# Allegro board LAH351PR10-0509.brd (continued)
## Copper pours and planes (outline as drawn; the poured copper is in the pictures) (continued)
LX2_NVVDD on BOTTOM (solid shape): 34.61,50.45 34.61,48.86 34.54,48.8 32.96,48.8 32.83,48.92 32.83,50.38 32.96,50.51 34.54,50.51
LX3_NVVDD on TOP (solid shape): 42.48,50.23 43.27,50.23 43.27,51.11 44.62,51.11 44.83,50.89 44.83,47.21 44.54,46.92 39.2,46.92 38.93,46.64 38.93,45.49 38.86,45.43 38.23,45.43 38.16,45.49 38.16,50.64 38.63,51.11 42.48,51.11
LX3_NVVDD on BOTTOM (solid shape): 42.29,50.45 42.29,48.86 42.23,48.8 40.64,48.8 40.51,48.92 40.51,50.38 40.64,50.51 42.23,50.51
LX4_NVVDD on TOP (solid shape): 50.24,50.24 50.95,50.24 50.95,51.11 52.24,51.11 52.45,50.89 52.45,47.21 52.16,46.92 46.82,46.92 46.55,46.64 46.55,45.49 46.48,45.43 45.85,45.43 45.78,45.49 45.78,50.64 46.25,51.11 50.24,51.11
LX4_NVVDD on BOTTOM (solid shape): 49.97,50.45 49.97,48.86 49.91,48.8 48.32,48.8 48.2,48.92 48.2,50.38 48.32,50.51 49.91,50.51
LX5_NVVDD on TOP (solid shape): 60.13,51.13 60.13,47.21 59.84,46.92 54.51,46.92 54.23,46.64 54.23,45.49 54.17,45.43 53.53,45.43 53.47,45.49 53.47,50.64 54.13,51.3 57.9,51.3 57.96,51.24 57.96,50.27 58.67,50.27 58.67,51.26 58.74,51.32 59.94,51.32
LX5_NVVDD on BOTTOM (solid shape): 57.78,50.57 57.78,48.99 57.72,48.92 56.13,48.92 56.01,49.05 56.01,50.51 56.13,50.64 57.72,50.64
LX6_NVVDD on TOP (solid shape): 65.76,51.2 65.76,50.33 66.47,50.33 66.47,51.18 66.54,51.25 67.78,51.25 67.88,51.15 67.88,47.27 67.5,46.89 62.19,46.89 61.98,46.68 61.98,45.43 61.91,45.37 61.15,45.37 61.09,45.43 61.09,50.83 61.53,51.27 65.68,51.27
LX6_NVVDD on BOTTOM (solid shape): 65.6,50.51 65.6,48.92 65.53,48.86 63.94,48.86 63.82,48.99 63.82,50.45 63.94,50.57 65.53,50.57
LX7_NVVDD on TOP (solid shape): 73.52,50.39 74.28,50.39 74.28,51.37 75.58,51.37 75.63,51.32 75.63,47.08 75.5,46.95 73.53,46.95 73.41,46.83 69.72,46.83 69.53,46.64 69.53,45.49 69.47,45.43 68.71,45.43 68.52,45.62 68.52,50.7 69.19,51.37 73.52,51.37
LX7_NVVDD on BOTTOM (solid shape): 73.34,50.7 73.34,49.11 73.28,49.05 71.69,49.05 71.56,49.18 71.56,50.64 71.69,50.76 73.28,50.76
LX8_NVVDD on TOP: 79.25,89.82 80.26,89.82 80.58,89.5 80.58,80.61 78.23,78.26 78.23,75.21 77.98,74.96 76.83,74.96 76.71,75.08 76.71,78.77 76.58,78.89 75.37,78.89 75.31,78.96 75.31,81.08 77.76,83.53 78.17,83.53 78.23,83.59 78.99,83.59 79.06,83.66 79.06,84.42 78.99,84.48 78.23,84.48 78.17,84.55 78.17,87.47 79.12,88.42 79.12,89.69
LX_1.0VS_VGAP on TOP (solid shape): 71.34,110.02 71.34,109.35 71.41,109.28 71.63,109.28 71.74,109.17 71.74,108.73 71.69,108.68 70.68,108.68 70.39,108.97 69.69,108.97 69.61,109.04 69.61,110.06 69.71,110.16 71.19,110.16
LX_1.0VS_VGAP on BOTTOM (solid shape): 72.29,109.34 72.29,105.91 72.04,105.66 71.53,105.66 71.47,105.72 71.47,107.47 70.93,108.01 68.23,108.01 67.94,108.3 67.94,109.76 68.01,109.82 71.82,109.82
LX_1.0VS_VGAP on IN4 (solid shape): 71.7,109.07 71.7,108.09 71.59,107.98 71.25,107.98 71.18,108.04 71.18,108.64 71.07,108.75 70.64,108.75 70.51,108.88 70.51,109.16 70.65,109.3 71.48,109.3
LX_3V on TOP: 65.02,23.4 66,22.42 68.45,22.42 68.47,22.41 68.47,21.88 68.43,21.85 67.09,21.85 66.9,21.65 66.9,19.62 66.7,19.42 63.31,19.42 63.22,19.51 63.22,21.82 64.26,22.86 64.26,24.44 64.34,24.51 64.92,24.51 65.02,24.41
LX_3V on BOTTOM: 65.07,23.9 65.56,23.9 65.61,23.85 65.61,22.84 64.9,22.13 64.14,22.13 63.25,23.01 63.25,23.03 63.14,23.03 62.92,23.26 62.92,24.27 63.02,24.37 64.6,24.37
LX_5V on TOP (solid shape): 56.2,25.43 56.2,20.16 55.18,19.14 55.18,16.98 54.23,16.03 52.26,16.03 52.07,16.22 52.07,19.84 52.48,20.25 54.32,20.25 55.63,21.55 55.63,25.43 55.75,25.55 56.07,25.55
LX_5V on BOTTOM (solid shape): 57.09,17.93 58.36,17.93 58.48,17.81 58.48,17.17 58.36,17.05 53.98,17.05 53.85,17.17 53.85,18.57 54.28,19 56.02,19
LX_+1.8VGS on TOP: 48.83,7.08 48.83,6.57 48.96,6.44 51.18,6.44 51.31,6.31 51.31,5.11 51.44,4.98 52.9,4.98 53.02,5.11 53.02,8.66 52.64,9.04 52.64,9.81 52.58,9.87 50.42,9.87 50.36,9.81 50.36,8.6
LX_CHG on BOTTOM (solid shape): 42.28,18.56 42.38,18.56 42.53,18.4 43.61,18.4 43.69,18.33 43.69,18.19 43.64,18.14 42.43,18.14 42.39,18.1 42.21,18.1 41.97,18.34 41.67,18.34 41.57,18.44 41.57,18.7 41.69,18.82 42.01,18.82
LX_CHG on TOP: 35.12,25.44 35.12,23.13 36.2,22.04 39.71,22.04 42.86,18.89 42.86,18.44 42.48,18.06 42.04,18.06 39.71,20.39 31.26,20.39 30.66,21 30.66,22.19 30.48,22.37 30.48,25.49 30.62,25.63 34.92,25.63
LX_CHG on BOTTOM: 38.61,21.36 39.5,21.36 39.62,21.24 39.62,20.79 39.5,20.67 37.02,20.67 36.35,21.34 35.42,21.34 35.18,21.1 35.18,19.84 34.99,19.65 31.75,19.65 31.37,20.03 31.37,22.28 32.25,23.16 32.25,25.33 32.71,25.78 34.44,25.78 34.95,25.27 34.95,23.89 35.32,23.52 37.85,23.52 38.23,23.14 38.23,21.74
LX_VCCIO on TOP (solid shape): 132.33,54.33 132.33,53.95 132.16,53.77 132.16,52.59 132.59,52.16 134.18,52.16 134.3,52.03 134.3,51.46 134.18,51.34 132.65,51.34 132.21,50.89 132.21,50.26 131.95,50 129.67,50 129.48,50.19 129.48,53.43 129.51,53.46 129.51,54.42 129.73,54.64 132.03,54.64
LX_VCCIO on BOTTOM (solid shape): 132.33,54.57 132.33,54.04 131.79,53.49 129.6,53.49 129.16,53.05 129.16,50.51 129.29,50.38 130,50.38 130.06,50.32 130.06,49.71 129.97,49.62 128.78,49.62 128.52,49.88 128.52,54.57 128.71,54.76 132.14,54.76
LX_VCCIO on TOP: 136.06,51.68 136.79,51.68 136.91,51.56 136.91,50.74 136.97,50.68 136.97,50.31 136.83,50.17 136.46,50.17 136.18,50.45 136.18,51.32 136,51.5 136,51.63
NVVDD_B on BOTTOM (solid shape): 21.26,37.75 21.58,37.56 21.89,37.75 25.72,37.75 26.16,37.3 26.16,35.62 26.11,35.56 15.75,35.56 15.69,35.63 15.69,37.66 15.77,37.75
NVVDD_B+ on TOP (solid shape): 52.74,44.13 52.74,41.7 52.1,41.06 52.1,38.74 51.84,38.48 49.96,38.48 49.81,38.64 49.81,41.23 50.16,41.58 50.16,42.89 50.04,43.02 48.7,43.02 48.64,43.08 48.64,44.16 48.7,44.22 52.64,44.22
NVVDD_B+ on TOP (solid shape): 37.47,44.03 37.47,42.41 36.75,42.41 36.75,41.06 36.2,40.5 36.2,38.7 36.04,38.55 34.46,38.55 34.32,38.69 34.32,41.24 34.99,41.91 34.99,42.89 34.86,43.02 33.53,43.02 33.46,43.08 33.46,44.16 33.53,44.22 37.27,44.22
NVVDD_B+ on TOP (solid shape): 79.76,43.84 79.76,41.61 79.72,41.57 79.72,39.43 79.44,39.16 76.95,39.16 76.72,39.39 71.82,39.39 71.67,39.54 71.67,40.15 71.77,40.25 72.56,40.25 73.15,40.85 73.15,42.89 73.03,43.02 71.69,43.02 71.63,43.08 71.63,44.16 71.69,44.22 76.01,44.22 76.33,44.54 79.06,44.54
NVVDD_B+ on TOP (solid shape): 45.09,44.1 45.09,41.06 44.8,40.78 44.3,40.78 44.12,40.59 44.12,38.64 43.93,38.45 41.91,38.45 41.85,38.51 41.85,39.4 42,39.55 42,41.13 42.19,41.32 42.33,41.32 42.55,41.53 42.55,42.89 42.42,43.02 41.08,43.02 41.02,43.08 41.02,44.16 41.08,44.22 44.96,44.22
NVVDD_B+ on TOP (solid shape): 29.01,43.88 29.72,43.88 30.05,43.55 30.05,41.47 29.64,41.06 29.07,41.06 28.78,40.77 28.78,38.65 28.99,38.43 29.5,38.43 29.75,38.18 29.75,34.54 29.65,34.44 26.87,34.44 26.48,34.84 26.48,35.65 25.92,36.21 25.92,39.08 26.53,39.69 26.53,40.4 26.64,40.52 26.64,41.21 27.43,42 27.43,42.89 27.3,43.02 25.97,43.02 25.91,43.08 25.91,44.16 25.97,44.22 28.66,44.22
NVVDD_B+ on BOTTOM (solid shape): 74.3,76.23 74.3,73.69 74.87,73.12 74.87,72.86 74.68,72.67 74.63,72.67 74.05,72.1 74.03,72.1 73.96,72.04 73.96,69.7 73.56,69.29 71.7,69.29 71.32,69.67 71.32,70.56 68.28,73.61 67.56,73.61 67.4,73.78 67.4,74.46 67.27,74.59 67.04,74.59 67.04,74.6 65.88,74.6 64.92,75.55 64.92,76.53 65.14,76.75 67.97,76.75 67.98,76.74 72.96,76.74 73.03,76.8 73.72,76.8
NVVDD_B+ on GND1 (solid shape): 73.91,76.61 73.91,74.13 74.61,73.43 74.8,73.43 74.93,73.31 74.93,72.93 74.74,72.74 72.83,72.74 72.52,73.05 72.52,74.13 72.9,74.51 72.9,76.67 73.09,76.86 73.66,76.86
NVVDD_B+ on TOP: 60.33,44.22 60.45,44.1 60.45,42.47 60.55,42.37 60.55,41.67 60.79,41.43 60.79,41.4 60.78,41.39 60.78,40.33 60.93,40.17 65.57,40.17 65.85,40.45 65.85,41.84 65.66,42.03 65.66,42.06 65.6,42.13 65.6,42.95 65.53,43.02 64.14,43.02 64.07,43.08 64.07,44.1 64.14,44.16 66.17,44.16 66.23,44.22 67.94,44.22 68.07,44.1 68.07,42.83 68.01,42.76 67.12,42.76 67.12,36.73 67.09,36.7 67.09,36.13 66.55,35.59 64.2,35.59 63.5,36.29 61.59,36.29 61.34,36.54 61.34,37.62 61.04,37.92 57.81,37.92 57.47,38.27 57.47,41.52 57.85,41.9 57.85,42.89 57.72,43.02 56.39,43.02 56.32,43.08 56.32,44.16 56.39,44.22
NVVDD_B+ on TOP: 73.03,76.8 73.91,76.8 74.1,76.61 74.1,73.94 74.99,73.05 74.99,71.34 74.8,71.15 71.44,71.15 71.37,71.21 71.37,74.96 71.63,75.21 72.64,75.21 72.9,75.47 72.9,76.67
NVVDD_B+ on BOTTOM: outline of 114 points within 18.67,31.65 80.07,44.35
NVVDD_B+ on IN1: 74.13,44.15 26.05,44.15 25.68,43.78 25.68,41.02 25.92,40.78 74.23,40.78 74.56,41.11 74.56,43.72
NVVDD_B+ on GND2: 72.64,72.54 74.68,72.54 74.93,72.8 74.93,73.18 74.8,73.31 74.3,73.31 74.17,73.43 74.17,74.32 73.79,74.7 72.77,74.7 72.52,74.45 72.52,72.67
NVVDD_B+ on IN2: 77.03,39.52 76.64,39.14 74.36,39.14 73.56,39.94 73.56,42.55 72.96,43.14 31.05,43.14 29.84,41.94 29.84,39.91 29.34,39.4 29.34,37.49 29.15,37.3 29.13,37.3 28.22,36.39 26.63,36.39 25.4,37.62 25.4,46.38 26.04,47.02 71.12,47.02 72.39,48.29 72.39,76.61 73.03,77.24 75.06,77.24 75.76,76.55 75.76,47.72 77.03,46.45
NVVDD_B+ on VCC: 25.59,43.61 26.27,44.29 76.98,44.29 77.41,43.86 77.41,39.57 76.67,38.83 30.57,38.83 28.09,36.35 27.03,36.35 25.59,37.79
NVVDD_B+ on IN4: 23.04,38.64 29.25,38.64 29.69,38.19 29.69,35.59 28.22,34.11 26.45,34.11 26.01,33.67 26.01,31.99 25.84,31.83 20.21,31.83 19.66,32.37 19.66,34.5 20.61,35.45 20.61,36.21
PEX_VDD_ENP on BOTTOM (solid shape): 70.55,104.23 70.55,104.1 70.36,103.91 70.36,102.96 71.17,102.15 71.17,101.6 71.02,101.45 68.15,101.45 68,101.6 68,102.19 69.34,103.53 69.34,104.1 69.53,104.29 70.48,104.29
PWM2_FBVDDQ on TOP: 15.58,40.38 16.03,40.82 16.12,40.82 16.24,40.69 16.24,40.02 15.89,39.66 13.82,39.66 13.73,39.75 13.73,40.33 13.78,40.38
SA_SW on TOP: 147.64,109.44 149.67,109.44 149.86,109.25 149.86,106.71 147.26,104.1 143.45,104.1 143.19,103.85 143.19,102.64 143.13,102.58 142.43,102.58 142.37,102.64 142.37,104.04 144.15,105.82 145.8,105.82 147.57,107.6 147.57,109.37
SNB1_NVVDD on BOTTOM (solid shape): 29.62,50.32 29.62,47.84 29.5,47.72 28.73,47.72 28.61,47.84 28.61,48.54 28.35,48.8 27.84,48.8 27.53,49.11 27.53,50.32 27.59,50.38 29.56,50.38
SNB2_NVVDD on BOTTOM (solid shape): 37.18,50.32 37.18,47.84 37.05,47.72 36.29,47.72 36.16,47.84 36.16,48.54 35.91,48.8 35.4,48.8 35.08,49.11 35.08,50.32 35.15,50.38 37.12,50.38
SNB3_NVVDD on BOTTOM (solid shape): 44.86,50.32 44.86,47.84 44.74,47.72 43.97,47.72 43.85,47.84 43.85,48.54 43.59,48.8 43.08,48.8 42.77,49.11 42.77,50.32 42.83,50.38 44.8,50.38
SNB4_NVVDD on BOTTOM (solid shape): 52.58,50.38 52.58,47.91 52.45,47.78 51.69,47.78 51.56,47.91 51.56,48.61 51.31,48.86 50.8,48.86 50.48,49.18 50.48,50.38 50.55,50.45 52.51,50.45
SNB5_NVVDD on BOTTOM (solid shape): 60.29,50.38 60.29,47.91 60.17,47.78 59.4,47.78 59.28,47.91 59.28,48.61 59.02,48.86 58.52,48.86 58.2,49.18 58.2,50.38 58.26,50.45 60.23,50.45
SNB6_NVVDD on BOTTOM (solid shape): 68.17,50.32 68.17,47.84 68.04,47.72 67.28,47.72 67.15,47.84 67.15,48.54 66.9,48.8 66.39,48.8 66.07,49.11 66.07,50.32 66.14,50.38 68.1,50.38
SNB7_NVVDD on BOTTOM (solid shape): 75.55,49.83 75.55,47.97 75.42,47.84 74.67,47.84 74.51,48 74.51,48.62 73.76,49.37 73.76,50.57 73.82,50.64 74.74,50.64
SNB8_NVVDD on TOP: 75.37,89.69 78.61,89.69 78.74,89.56 78.74,88.42 78.23,87.91 75.44,87.91 75.18,88.17 75.18,89.5
SNB_1.0VS_VGAP on TOP (solid shape): 68.94,109.97 68.94,109.07 69.25,108.77 69.25,107.9 69.2,107.85 68.14,107.85 67.96,108.03 67.96,109.92 68.06,110.01 68.9,110.01
SNB_1.2V on BOTTOM (solid shape): 150.37,61.43 150.37,60.73 150.5,60.61 151.32,60.61 151.38,60.54 151.38,59.97 151.26,59.84 148.21,59.84 148.13,59.92 148.13,61.47 148.22,61.56 150.24,61.56
SNB_+1.8VGS on TOP: 53.25,10.31 51.75,10.31 51.56,10.51 51.56,11.58 51.68,11.71 53.79,11.71 53.99,11.51 53.99,10.23 53.9,10.14 53.4,10.14 53.35,10.19 53.35,10.21
SNB_+1VALWP on BOTTOM (solid shape): 131.44,27.08 131.44,25.24 131.38,25.17 130.81,25.17 130.68,25.3 130.68,26 130.62,26.06 129.92,26.06 129.79,26.19 129.79,27.02 129.98,27.21 131.32,27.21
SNB_VCCIO on BOTTOM (solid shape): 132.14,51.97 132.14,50.95 132.08,50.89 129.54,50.89 129.41,51.02 129.41,52.73 129.79,53.11 131,53.11
SW_1.2V on TOP (solid shape): 149.43,50.52 149.43,50.13 148.95,49.65 148.95,49.42 147.87,48.34 147.8,48.34 147.68,48.47 147.68,49.16 147.87,49.35 148.11,49.35 148.37,49.62 148.37,50.47 148.54,50.64 149.31,50.64
SW_1.2V on TOP (solid shape): 150.05,61.31 150.05,56.99 150.5,56.54 151.18,56.54 151.28,56.44 151.28,55.87 151.19,55.78 150.37,55.78 150.05,55.46 150.05,53.3 149.8,53.05 145,53.05 144.82,53.23 144.82,58.14 145.22,58.55 145.22,61.37 145.48,61.62 149.73,61.62
SW_1.2V on BOTTOM (solid shape): 147.7,61.5 147.7,59.53 147.96,59.27 149.54,59.27 149.73,59.08 149.73,58.45 149.54,58.26 145.99,58.26 145.61,58.64 145.61,61.31 145.86,61.56 147.64,61.56
SW_1.2V on IN1 (solid shape): 150.18,61.11 150.18,52.92 149.54,52.29 149.54,50.19 149.35,50 148.59,50 148.4,50.19 148.4,52.42 149.1,53.11 149.1,59.65 148.72,60.04 146.05,60.04 145.8,60.29 145.8,61.11 145.99,61.31 149.99,61.31
SW_+1VALWP on TOP (solid shape): 131.38,33.77 131.38,33.43 131.76,33.05 134.75,33.05 134.81,32.98 134.81,32.54 134.62,32.35 133.41,32.35 132.65,31.59 132.65,27.33 132.4,27.08 129.29,27.08 128.97,27.4 128.97,33.68 129.22,33.94 131.22,33.94
SW_+1VALWP on BOTTOM (solid shape): 131.59,36.23 131.59,33.89 131.38,33.68 131.38,32.22 131.32,32.16 129.92,32.16 129.54,31.78 129.54,30.63 129.53,30.63 129.53,29.06 129.8,28.79 131.32,28.79 131.44,28.67 131.44,27.65 131.32,27.52 129.22,27.52 128.83,27.91 128.83,28.27 128.73,28.37 128.73,28.37 128.64,28.47 128.64,31.79 128.52,31.9 128.52,36.22 128.71,36.41 131.41,36.41
SW_+1VALWP on IN1: 134.49,30.25 135.25,30.25 135.38,30.13 135.38,29.87 135.25,29.75 133.99,29.75 133.73,30 133.73,33.81 133.54,34 131.83,34 131.19,33.37 130.87,33.37 130.81,33.43 130.81,34.13 131.38,34.7 133.92,34.7 134.37,34.25 134.37,30.38
TBT_SVR_IND on BOTTOM: 84.01,146.78 85.72,146.78 85.85,146.65 85.85,146.2 85.72,146.08 84.45,146.08 84.39,146.14 84.39,146.27 84.26,146.4 84.01,146.4 83.95,146.46 83.95,146.71
TBT_SVR_IND on IN1: 70.74,150.52 84.58,150.52 85.93,149.18 85.93,146.33 85.78,146.18 84.94,146.18 83.13,147.98 73.72,147.98 73.47,148.24 70.68,148.24 70.29,148.62 70.29,150.08
UD1_ISL95338_1 on TOP: 54.29,37.62 55.18,37.62 55.31,37.49 55.31,36.03 55.63,35.71 56.71,35.71 56.96,35.46 56.96,35.33 57.4,34.89 57.4,32.92 57.09,32.6 55.31,32.6 55.18,32.73 55.18,34.13 55.37,34.32 56.13,34.32 56.26,34.44 56.26,34.95 56.07,35.14 55.18,35.14 54.23,36.1 54.23,37.56
UD1_ISL95338_1 on TOP: 50.04,38.16 54.88,38.16 55.35,37.7 55.35,36.07 55.18,35.91 51.22,35.91 50.81,35.5 50.81,33.66 50.46,33.31 50.06,33.31 49.88,33.13 49.88,31.06 50.75,30.19 51.38,30.19 51.55,30.03 51.55,28.11 51.35,27.9 50.72,27.9 50.46,27.64 50.46,25.39 50.32,25.25 49.61,25.25 49.38,25.48 49.38,29.87 48.77,30.48 48.77,35.49 48.58,35.68 47.88,35.68 47.64,35.92 47.64,37.92 48.08,38.37 49.83,38.37
UD1_ISL95338_1 on BOTTOM: 51.96,38.61 49.95,38.61 49.76,38.43 46.3,38.43 46.2,38.32 46.2,35.57 46.29,35.47 48.37,35.47 48.83,35.02 48.83,30.18 48.91,30.1 48.91,24.84 48.97,24.78 49.97,24.78 49.99,24.8 50.44,24.8 50.74,25.1 50.74,27.99 50.55,28.18 50.55,32.73 52.24,34.42 52.24,35.61 52.7,36.08 52.7,37.98 52.08,38.6 51.96,38.6
UG1_ISL95338_1 on BOTTOM: 55.18,34.32 55.31,34.44 55.37,34.44 55.94,33.87 55.94,32.86 55.88,32.79 55.75,32.79 55.69,32.86 55.69,33.68 55.18,34.19
UG2_ISL95338_1 on IN3 (solid shape): 53.05,31.31 53.05,31.13 52.85,30.93 52.85,30.49 52.54,30.18 52.31,30.18 52.13,30.36 52.13,31.05 52.44,31.36 53,31.36
UG_+1VALWP on BOTTOM (solid shape): 132.37,33.59 132.37,32.25 132.21,32.1 131.76,32.1 131.64,32.22 131.64,33.56 131.83,33.75 132.21,33.75
UG_+1VALWP on IN1 (solid shape): 133.6,33.43 133.6,29.75 133.79,29.56 135.25,29.56 135.38,29.43 135.38,29.11 135.25,28.98 133.48,28.98 133.03,29.43 133.03,32.92 132.72,33.24 131.76,33.24 131.64,33.37 131.64,33.56 131.83,33.75 133.29,33.75
UG_CHG on BOTTOM: 41.66,19.33 42.42,18.57 43.62,18.57 43.69,18.63 43.69,18.76 43.62,18.82 42.8,18.82 41.59,20.03 39.88,20.03 39.56,20.35 38.73,20.35 38.67,20.28 38.67,19.4 38.73,19.33
UG_CHG_R on BOTTOM (solid shape): 36.39,21.05 36.39,20.54 36.51,20.41 37.91,20.41 37.97,20.35 37.97,19.46 37.91,19.4 35.81,19.4 35.69,19.52 35.69,21.05 35.81,21.17 36.26,21.17
N20124859 on TOP: 84.52,146.01 84.9,146.01 86.11,144.81 86.11,143.09 85.98,142.97 85.47,142.97 85.41,143.03 85.41,144.43 84.39,145.44 84.39,145.89
N20764785 on TOP: 93.22,46.32 93.6,46.32 93.66,46.26 93.66,46.07 93.54,45.94 93.28,45.94 93.15,45.81 92.33,45.81 92.08,46.07 92.08,46.26 92.27,46.45 92.52,46.45 92.77,46.19 93.09,46.19
N22948364 on TOP (solid shape): 2.51,17.75 2.58,17.73 2.64,17.72 2.82,17.72 2.88,17.73 2.94,17.74 3.19,17.5 3.19,16.79 2.79,16.4 2.79,15.32 2.69,15.22 2.19,15.22 1.61,15.8 1.61,17.47 1.89,17.75
N22948383 on TOP (solid shape): 5.97,18.67 5.97,17.91 5.97,17.91 5.97,17.68 5.83,17.55 5.31,17.55 5.07,17.78 4.45,17.78 4.32,17.91 4.32,18.61 4.51,18.8 5.84,18.8
N24660253 on TOP: 99.75,17.98 99.58,17.81 99.58,16.36 99.67,16.26 102.14,16.26 102.21,16.32 102.21,18.73 102.1,18.84 99.81,18.84 99.75,18.77
N24698323 on IN1 (solid shape): 53.47,90.9 53.47,90.83 53.34,90.71 51.94,90.71 51.69,90.45 51.44,90.45 51.37,90.52 51.37,90.9 51.5,91.02 53.34,91.02
N25775725 on TOP: 25.08,19.14 27.3,19.14 27.5,18.95 27.5,18.44 27.3,18.25 25.02,18.25 24.89,18.38 24.89,18.95
N25775727 on TOP: 26.04,11.9 27.57,11.9 27.57,13.08 27.74,13.25 30.52,13.25 30.85,12.92 34.54,12.92 34.73,13.11 34.73,18.38 34.62,18.49 30.34,18.49 29.78,17.93 25.27,17.93 24.89,17.55 24.89,14.63 25.84,13.68 25.84,12.09
N25775797 on TOP (solid shape): 43.18,13.55 43.18,12.6 42.93,12.35 40.26,12.35 40.2,12.41 40.2,13.55 40.45,13.81 42.93,13.81
N25775832 on TOP: 22.01,24.42 22.28,24.16 22.82,24.16 22.92,24.06 22.92,23.92 22.93,23.91 22.93,23.54 22.88,23.5 20.69,23.5 20.05,24.13 20.05,26.2 20.42,26.57 21.72,26.57 22.01,26.28
N25775833 on BOTTOM: 20.26,25.75 23.88,25.75 24.07,25.55 24.07,24.54 24.38,24.22 25.84,24.22 26.16,24.54 26.16,25.49 26.42,25.75 29.27,25.75 29.46,25.55 29.46,24.03 29.08,23.65 28.32,23.65 28.13,23.46 28.13,22.38 27.94,22.19 23.81,22.19 23.62,22.38 23.62,23.4 23.37,23.65 22.42,23.65 22.16,23.4 22.16,22.38 21.97,22.19 18.93,22.19 18.81,22.31 18.81,23.54 18.92,23.65 19.62,23.65 20,24.03 20,25.49
N25775859 on TOP: 24.76,25.36 24.76,25.13 24.61,24.98 23.52,24.98 23.25,25.25 23.11,25.25 22.85,25.52 22.49,25.52 22.42,25.59 22.42,26.49 22.44,26.52 23.11,26.52 23.23,26.4 23.23,26.07 23.52,25.79 24.34,25.79
N25775859 on BOTTOM: 24.45,25.75 25.46,25.75 25.59,25.62 25.59,24.67 25.4,24.48 24.45,24.48 24.26,24.67 24.26,25.55
N25775859 on BOTTOM: 17.84,25.75 19.24,25.75 19.43,25.55 19.43,24.6 19.24,24.41 17.91,24.41 17.72,24.6 17.72,25.62
N25775862 on BOTTOM: 16.13,20.47 17.91,20.47 18.73,21.3 29.34,21.3 29.72,20.92 29.72,17.11 29.34,16.73 16.26,16.73 15.88,17.11 15.88,20.22
N25777570 on TOP: 63.65,24.52 63.48,24.52 63.08,24.12 60.7,24.12 60.58,23.99 60.58,23.06 60.6,23.04 59.93,22.38 59.92,22.38 59.92,21.67 60.06,21.53 60.69,21.53 60.73,21.57 60.73,22.22 61.23,22.71 62.89,22.71 63.73,23.55 63.73,24.45
N25777686 on TOP: 47.92,22.58 49.3,22.58 49.41,22.48 49.41,21.28 49.18,21.05 48.11,21.05 47.84,21.31 47.84,22.51
N26232649 on BOTTOM (solid shape): 103.86,34.98 103.86,33.83 103.67,33.64 103.03,33.64 102.78,33.9 102.78,34.91 102.97,35.1 103.73,35.1
N26991157 on TOP: 12.12,41.21 12.73,41.21 12.83,41.11 12.83,39.55 12.7,39.42 12.17,39.42 11.93,39.66 11.93,41.02
N26991610 on TOP (solid shape): 2.97,61.08 2.97,59.2 2.71,58.93 1.79,58.93 1.69,59.03 1.69,61.06 1.85,61.23 2.82,61.23
N27425503 on TOP (solid shape): 14.03,65.75 14.03,63.59 14.99,62.64 14.99,61.31 14.93,61.25 13.96,61.25 13.96,60.41 14.92,60.41 14.99,60.35 14.99,58.19 14.63,57.84 10.82,57.84 10.48,57.5 9.6,57.5 9.46,57.64 9.46,57.99 9.45,58 9.44,58 9.39,58.05 9.39,61.76 9.21,61.94 8.04,61.94 7.96,62.02 7.96,62.77 8.18,62.98 10.69,62.98 11.37,63.65 11.37,65.56 11.75,65.94 13.84,65.94
N27669103 on TOP: 16.47,40.82 16.68,40.82 16.76,40.73 16.76,39.69 16.01,38.94 15.47,38.94 15.43,38.98 15.43,39.52 15.49,39.59 15.88,39.59 16.34,40.06 16.34,40.69
N27693415 on BOTTOM: 91.19,133.89 92.28,133.89 92.94,133.23 92.94,132.44 92.81,132.31 91.85,132.31 91.19,132.97
N27693535 on BOTTOM: 99.71,133.69 99.71,132.45 99.8,132.36 101.56,132.36 101.61,132.42 101.61,133.67 101.53,133.75 99.77,133.75
N27693577 on BOTTOM: 108.1,133.91 109.25,133.91 109.91,133.25 109.91,132.49 109.75,132.34 108.69,132.34 108.05,132.97 108.05,133.86
N27693691 on TOP: 15.67,41.23 12.98,41.23 12.89,41.14 12.89,40.67 13.06,40.5 15.34,40.5 15.79,40.95 15.79,41.11
N27694593 on TOP: 129.03,121.5 129.03,121.19 129.1,121.12 130.05,121.12 130.49,120.68 131.06,120.68 131.13,120.74 131.13,121.5 131.06,121.57 129.1,121.57
N28888311 on BOTTOM: 83.67,133.76 85.06,133.76 85.45,133.38 85.45,132.34 85.27,132.16 84.25,132.16 83.59,132.82 83.59,133.68
N28891277 on TOP: 98.68,135.66 99.38,135.66 99.82,135.22 100.84,135.22 100.97,135.09 100.97,134.33 100.9,134.27 98.23,134.27 98.04,134.46 98.04,135.03
N28898663 on TOP: 130.68,131.79 131.38,131.79 131.95,131.22 131.95,130.46 131.32,129.82 131.32,129.19 131.19,129.06 130.62,129.06 130.49,129.19 130.49,131.54 130.56,131.6 130.56,131.66
N28905385 on TOP: 132.08,122.84 132.59,122.84 133.16,122.27 134.37,122.27 134.94,121.69 134.94,121.06 134.81,120.93 134.49,120.93 134.3,120.74 134.3,119.85 134.18,119.73 133.73,119.73 133.57,119.88 133.57,120.96 132.65,121.88 132.08,121.88 131.95,122.01 131.95,122.71
N29102370 on TOP (solid shape): 72.96,42.7 72.96,40.88 72.57,40.49 71.82,40.49 71.76,40.55 71.76,41.32 71.95,41.51 72.35,41.51 72.64,41.8 72.64,42.7 72.71,42.76 72.9,42.76
N29676897 on BOTTOM: 35.94,25.49 36.77,25.49 36.89,25.36 36.89,23.97 36.77,23.84 36,23.84 35.81,24.03 35.81,25.36
N32296413 on BOTTOM (solid shape): 88.2,125.85 88.2,123.41 88.14,123.34 87.12,123.34 87,123.47 87,125.87 87.16,126.04 88.01,126.04
N32879277 on BOTTOM (solid shape): 93.71,125.91 93.71,123.48 93.6,123.37 91.78,123.37 91.68,123.47 91.68,125.91 91.81,126.04 93.59,126.04
N32879345 on BOTTOM (solid shape): 100.86,125.81 100.86,125.43 100.9,125.4 100.9,123.4 100.75,123.26 99.82,123.26 99.66,123.42 99.66,125.87 99.78,126 100.67,126
N32879406 on BOTTOM (solid shape): 108.78,125.63 108.78,123.17 108.61,123 106.69,123 106.44,123.26 106.44,124.56 107.7,125.82 108.58,125.82
N32879443 on BOTTOM: 119.55,130.13 120.41,130.13 120.56,129.97 120.56,129.28 120.82,129.02 120.82,127.07 120.69,126.94 118.9,126.94 118.52,127.32 118.52,128.74 119.33,129.56 119.33,129.91
N32879490 on BOTTOM (solid shape): 123,125 123.67,125 123.72,124.95 123.72,124.24 123.7,124.21 122.57,124.21 122.11,123.75 120.5,123.75 120.33,123.92 120.33,125 120.5,125.16 122.83,125.16
N32879537 on BOTTOM (solid shape): 144.73,93.37 144.73,92.76 144.96,92.53 146.49,92.53 146.86,92.17 146.86,91.35 146.65,91.14 144.08,91.14 143.84,91.38 143.84,93.16 144.12,93.44 144.67,93.44
N32879582 on BOTTOM (solid shape): 144.35,107.15 144.35,105.51 143.94,105.11 143.94,104.12 143.87,104.05 142.95,104.05 141.97,105.03 141.97,107.2 142.25,107.48 144.02,107.48
N32883714 on TOP: 17.96,40.82 18.11,40.82 18.26,40.67 18.26,39.42 18.55,39.13 18.55,38.06 18.38,37.89 17.64,37.89 17.56,37.96 17.56,38.93 17.82,39.18 17.82,40.68
N32888909 on BOTTOM (solid shape): 18.1,47.84 18.1,46.76 18.03,46.7 17.53,46.7 16.95,47.27 16.51,47.27 16.45,47.34 16.45,47.84 16.57,47.97 17.97,47.97

Small or netless copper shapes (teardrops, artwork), in the pictures only: 33 on TOP, 18 on BOTTOM, 1 on IN1, 8 on GND4, 2 on GND2, 1 on IN3, 3 on IN4

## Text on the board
Ref Des/Silkscreen Bottom: SSD-1(PCIE+SATA) | FBEAM LAN/B | 17ONLY | SSD-2(PCIE ONLY) | FBEAM WLAN/B | RTC | BATTERY | EDP | KB | DC IN | 12V | FAN | FAN12V
User.Comments: LA-H351P | EDQ51 | Sunny | 2019-05-09 | 2020-05-09 | 1.0(A00)
Ref Des/Silkscreen Top: EDQ71 TP | EDQ51 TP | JIO1.1 | JIO2.1
GND5: GND5
XSECTION_CHART: *  SURFACE - AIR 0 MIL | *  DIELECTRIC - FR-4 0.8 MIL | L1: TOP CONDUCTOR - COPPER 1.42 MIL | *  DIELECTRIC - FR-4 1.9 MIL | L2: GND1 CONDUCTOR - COPPER 0.91 MIL | *  DIELECTRIC - FR-4 1.97 MIL | L3: IN1 CONDUCTOR - COPPER 0.91 MIL | *  DIELECTRIC - FR-4 2.86 MIL | L4: GND2 CONDUCTOR - COPPER 1.3 MIL | *  DIELECTRIC - FR-4 2.74 MIL | L5: IN2 CONDUCTOR - COPPER 1.25 MIL | *  DIELECTRIC - FR-4 2.5 MIL | L6: GND3 CONDUCTOR - COPPER 2.5 MIL | *  DIELECTRIC - FR-4 4.3 MIL | L7: VCC CONDUCTOR - COPPER 2.5 MIL | L8: IN3 CONDUCTOR - COPPER 1.25 MIL | L9: GND4 CONDUCTOR - COPPER 1.3 MIL | L10: IN4 CONDUCTOR - COPPER 0.91 MIL | L11: GND5 CONDUCTOR - COPPER 0.91 MIL | L12: BOTTOM CONDUCTOR - COPPER 1.42 MIL | DESIGN CROSS SECTION CHART | ___________________________ | TOTAL THICKNESS 46.42 MIL | 1-12 | 1-2 | 1-4 | 1-3 | 2-4 | 3-4 | 4-5 | 4-9 | 8-9 | 9-12 | 9-10 | 9-11 | 10-12 | 10-11 | 11-12
User.45: trace Width | Width/space | 4.8mil | 3.4mil | 2.3mil | 3.2mil | 3.39/2.55 | 3.3/4.7 | 3.5 / 4.5 | 3 / 5 | 2.7 / 5.3 | 3.2 / 4.8 | 2.2 / 6.1 | 2.6 / 5.4 | L4/L6 | L9/L11 | L11 | L11-GND5 | L12-BOT | 40 ohm | 50 ohm | 72 ohm | 80 ohm | 85 ohm | 100 ohm | FIGURE | SIZE | 8.0 | 16.0 | 20.0 | 22.0 | 71.0 | 90.0 | 102.0 | 146.0 | 157.0 | 30.0 | 35.0 | 39.0 | 43.0 | 47.0 | 57.0 | 63.0 | 106.0 | 47.0x26.0 | 49.0x26.0 | 55.0x28.0 | 55.0x39.0 | 63.0x24.0 | 71.0x28.0 | 79.0x35.0 | 87.0x39.0 | 169.0x146.0 | 37.0x30.0 | DRILL CHART: TOP to BOTTOM | ALL UNITS ARE IN MILS | TOLERANCE | +3.0/-3.0 | +2.0/-2.0 | PLATED | NON-PLATED | QTY | 3951 | 12 | 78 | 19 | 1 | 6 | 4 | 2 | 4.0 | DRILL CHART: GND2 to GND4 | DRILL CHART: TOP to GND1 | DRILL CHART: TOP to IN1 | DRILL CHART: TOP to GND2 | DRILL CHART: GND2 to IN2 | DRILL CHART: GND1 to GND2 | DRILL CHART: IN1 to GND2 | +1.0/-1.0 | 4347 | 855 | 1268 | 4633 | 205 | 177 | 269 | DRILL CHART: GND4 to IN4 | DRILL CHART: IN3 to GND4 | DRILL CHART: GND4 to GND5 | DRILL CHART: GND5 to BOTTOM | DRILL CHART: IN4 to BOTTOM | DRILL CHART: GND4 to BOTTOM | DRILL CHART: IN4 to GND5 | 787 | 175 | 215 | 783 | 426 | 2485
